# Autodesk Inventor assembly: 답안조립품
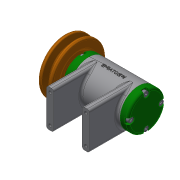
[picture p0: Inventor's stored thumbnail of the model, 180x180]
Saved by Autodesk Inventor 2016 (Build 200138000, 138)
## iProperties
Created: 2020-07
Part Number: 답안조립품
Document SubType Name: Assembly
Designer: user
Author: user
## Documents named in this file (15)
- C:\Users\user\Desktop\700706V1005\답안조립품.iam
- C:\Users\user\Desktop\700706V1005\본체.ipt
- C:\Users\user\Desktop\700706V1005\베어링 6002.ipt
- C:\Users\user\Desktop\700706V1005\앞커버.ipt
- C:\Users\user\Desktop\700706V1005\뒤커버.ipt
- C:\Users\user\Desktop\700706V1005\축.ipt
- C:\Users\user\Desktop\700706V1005\오일 실 15 25 7.ipt
- C:\Users\user\Desktop\700706V1005\Ű 3x3x12.ipt
- C:\Users\user\Desktop\700706V1005\V벨트풀리.ipt
- C:\Users\user\Desktop\700706V1005\와셔 8x17.ipt
- C:\Users\user\Desktop\700706V1005\스프링와셔 8.ipt
- C:\Users\user\Desktop\700706V1005\너트 M8.ipt
- C:\Users\user\Desktop\700706V1005\와셔 6x11.5.ipt
- C:\Users\user\Desktop\700706V1005\볼트 M6x8.ipt
- C:\Users\user\Desktop\700706V1005\볼트 M4x12.ipt
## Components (2 placed, 2 different names)
1. Ű 3x3x12:1
2. V벨트풀리:1
